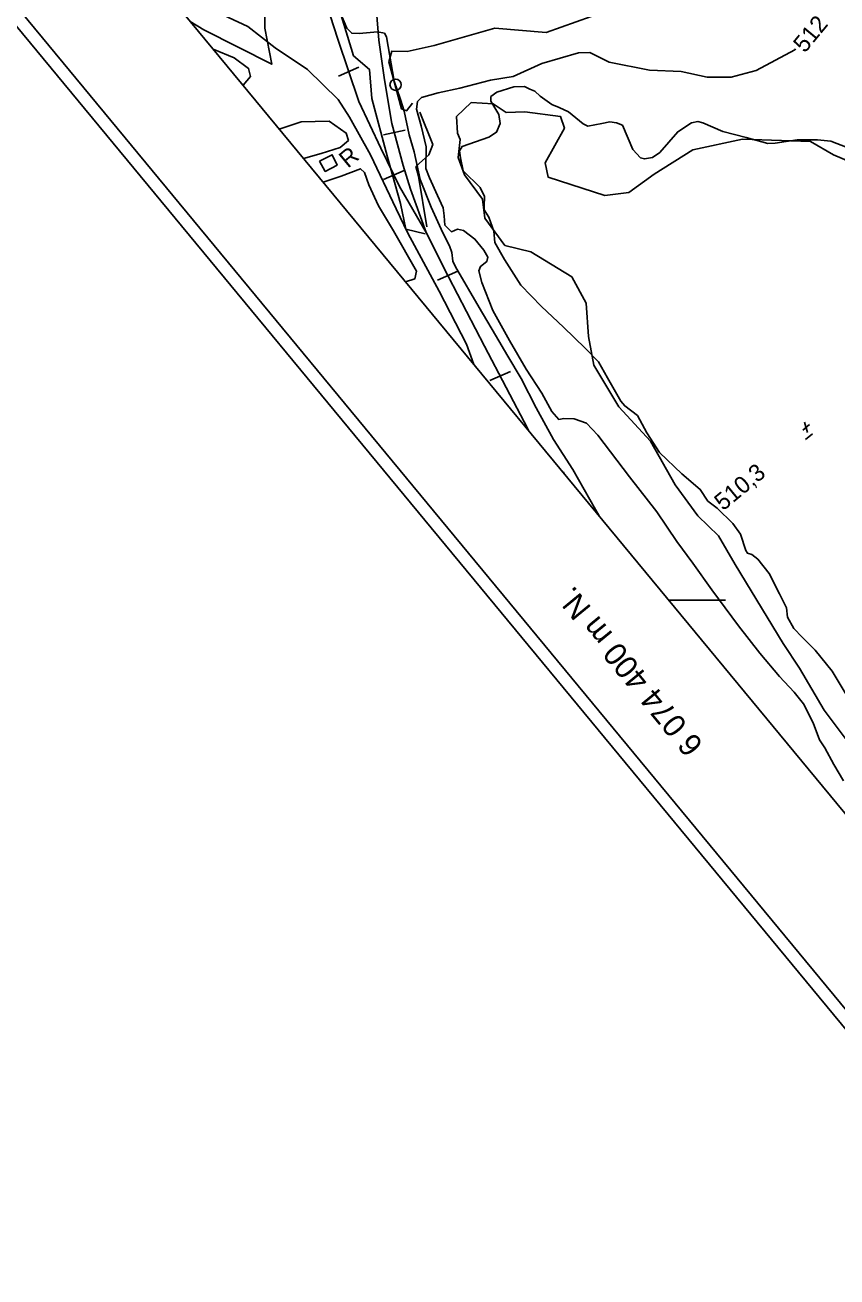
# Model space of a CAD drawing. Extents: x 347059 to 352153, y 6073752 to 6078601.
# Drawn here: x 348064.6 to 348279.8, y 6074220.5 to 6074552.6 of the extents above; entities that cross this region are included whole.
import ezdxf

# ---------------------------------------------------------------- set-up
doc = ezdxf.new("R2010")
doc.units = 0
for name, color, linetype in [('Level 1', 7, 'Continuous'), ('Level 2', 7, 'Continuous'), ('Level 23', 7, 'Continuous'), ('Level 3', 7, 'Continuous'), ('Level 31', 7, 'Continuous'), ('Level 36', 7, 'Continuous'), ('Level 4', 7, 'Continuous'), ('Level 44', 7, 'Continuous'), ('Level 60', 7, 'Continuous'), ('Level 61', 7, 'Continuous')]:
    doc.layers.add(name, color=color, linetype=linetype)

msp = doc.modelspace()

# ---------------------------------------------------------------- linework, layer by layer
at = {"layer": 'Level 1'}
for points in [[(348114.45, 6074546.2), (348119.99, 6074543.87), (348123.83, 6074541.07), (348124.38, 6074538.97), (348122.37, 6074536.61)], [(348131.99, 6074524.96), (348137.81, 6074526.94), (348145.22, 6074527.06), (348149.75, 6074523.92), (348150.32, 6074521.98), (348148.13, 6074520.13), (348143.07, 6074518.51), (348138.39, 6074517.22)], [(348143.59, 6074510.93), (348148.38, 6074512.54), (348153.47, 6074514.45), (348154.55, 6074513.49), (348155.73, 6074510.19), (348158.32, 6074504.59), (348162.28, 6074498), (348168.4, 6074487.34), (348167.89, 6074485.26), (348165.47, 6074484.45)]]:
    msp.add_lwpolyline(points, dxfattribs=at)
at = {"layer": 'Level 2'}
for points in [[(348145.31, 6074562.71), (348149.92, 6074551.73), (348151.18, 6074550.39), (348153.13, 6074550.3), (348158.05, 6074550.75), (348159.87, 6074550.4), (348160.44, 6074549.41), (348162.45, 6074537.69), (348164.15, 6074532.83), (348165.13, 6074529.77), (348166.43, 6074523.49), (348167.72, 6074518.96), (348169.37, 6074511.63), (348172.24, 6074504.27), (348175.31, 6074497.48), (348177.13, 6074494.06), (348177.71, 6074492.27), (348177.95, 6074489.93), (348178.69, 6074488.41), (348184.98, 6074477.65), (348189.31, 6074470.32), (348192.57, 6074464.78)], [(348113.37, 6074556.93), (348123.65, 6074552.15), (348130.88, 6074546.54), (348139.44, 6074540.77), (348147.55, 6074532.83), (348150.56, 6074528.14), (348156.2, 6074518.14), (348163.01, 6074503.86), (348166.02, 6074497.37)], [(348217.52, 6074543.71), (348214.32, 6074545.28), (348211.27, 6074545.24), (348201.55, 6074542.34), (348194.02, 6074538.89), (348188, 6074537.93), (348179.86, 6074535.84), (348174.11, 6074534.57), (348169.66, 6074533.34), (348168.63, 6074532.33)], [(348268.88, 6074546.23), (348268.66, 6074546.02), (348258.37, 6074540.48), (348251.79, 6074538.77), (348245.42, 6074538.71), (348238.52, 6074540.23), (348230.16, 6074540.63), (348219.4, 6074542.75), (348217.52, 6074543.71)], [(348168.63, 6074532.33), (348168.39, 6074530.24), (348169.56, 6074525.85), (348170.91, 6074520.29), (348170.81, 6074514.55), (348171.84, 6074512.06), (348173.92, 6074507.38), (348175.47, 6074504.12), (348175.66, 6074502), (348175.89, 6074499.5), (348177.63, 6074497.76), (348179.21, 6074498.43), (348180.84, 6074498.08), (348183.85, 6074495.79), (348186.22, 6074492.83), (348187.23, 6074491), (348186.99, 6074489.86), (348185.29, 6074488.54), (348184.9, 6074487.41), (348185.67, 6074484.29), (348188.61, 6074476.85), (348193.04, 6074468.91), (348197.42, 6074461.35), (348201.62, 6074454.96), (348204.26, 6074450.09), (348206.05, 6074447.98), (348207.45, 6074448.23), (348210.19, 6074448.15), (348213.43, 6074447.01), (348216.43, 6074443.78), (348224.81, 6074432.76), (348232.1, 6074423.5), (348237.4, 6074415.58), (348241.66, 6074409.88), (348246.68, 6074402.79), (348253.69, 6074393.2), (348259.36, 6074385.99), (348264.6, 6074379.77), (348268.48, 6074375.63), (348270.93, 6074372.57), (348273.56, 6074367.53), (348275.22, 6074363), (348276.65, 6074360.84), (348278.98, 6074356.47), (348281.6, 6074352.09)], [(348166.02, 6074497.37), (348174.35, 6074481.97), (348181.59, 6074467.9), (348183.6, 6074462.51)], [(348192.57, 6074464.78), (348196.11, 6074458.79), (348200.11, 6074451.05), (348204.65, 6074442.68), (348209.79, 6074434.7), (348215.8, 6074424.1), (348216.77, 6074422.37)]]:
    msp.add_lwpolyline(points, dxfattribs=at)
at = {"layer": 'Level 23'}
for points in [[(348170.93, 6074497.59), (348163.82, 6074509.8), (348158.89, 6074519.94), (348153.07, 6074532.32), (348147.46, 6074548.86), (348144.53, 6074558.12), (348140.41, 6074572.6), (348139.1, 6074584.7)], [(348198.25, 6074444.78), (348197.9, 6074445.44), (348186.42, 6074467.4), (348176.81, 6074485.77), (348170.93, 6074497.59), (348166.73, 6074509.01), (348164.82, 6074515.35), (348161.82, 6074526.5), (348159.85, 6074538.04), (348158.35, 6074548.56), (348157.46, 6074559.44)], [(348153.1, 6074541.4), (348147.68, 6074539.04)], [(348165.37, 6074524.68), (348159.58, 6074523.46)], [(348165.06, 6074514.02), (348159.64, 6074511.65)], [(348179.34, 6074487.32), (348173.91, 6074484.95)], [(348193.25, 6074460.7), (348187.83, 6074458.34)]]:
    msp.add_lwpolyline(points, dxfattribs=at)
at = {"layer": 'Level 3'}
for p, q in [((348271.21, 6074447.28), (348272.04, 6074444.53)), ((348270.75, 6074445.15), (348272.56, 6074446.64)), ((348271.47, 6074442.63), (348273.32, 6074444.16))]:
    msp.add_line(p, q, dxfattribs=at)
at = {"layer": 'Level 31'}
msp.add_lwpolyline([(348142.63, 6074516.5), (348146.02, 6074518.19), (348147.28, 6074515.42), (348144.18, 6074513.74), (348142.63, 6074516.5)], dxfattribs=at)
at = {"layer": 'Level 36'}
msp.add_circle((348162.81, 6074536.75), 1.5, dxfattribs=at)
at = {"layer": 'Level 4'}
for points in [[(348196.02, 6074483.59), (348191.68, 6074490.43), (348189.13, 6074494.93), (348188.83, 6074497.91), (348187.56, 6074501.59), (348186.27, 6074503.6), (348186.31, 6074504.54), (348186.38, 6074507.07), (348185.2, 6074509.48), (348180.72, 6074513.95), (348180.05, 6074517.37), (348179.77, 6074519.24), (348180.49, 6074520.37), (348182.23, 6074520.99), (348187.56, 6074522.8), (348189.61, 6074524.13), (348190.57, 6074526.5), (348190.17, 6074528.87), (348188.07, 6074532.39), (348188.1, 6074533.61), (348189.64, 6074534.75), (348194.2, 6074536.22), (348196.96, 6074536.25), (348198.37, 6074535.55), (348199.72, 6074535.01), (348201.16, 6074533.73), (348204.21, 6074531.53), (348206.18, 6074530.69), (348208.67, 6074529.6), (348212.52, 6074526.34), (348213.82, 6074525.77), (348217.46, 6074526.46), (348219.63, 6074526.92), (348221.42, 6074526.68), (348222.96, 6074526), (348225.7, 6074519.56), (348227.75, 6074517.36), (348228.83, 6074517.06), (348230.89, 6074517.48), (348232.85, 6074518.74), (348237.62, 6074524.29), (348241.29, 6074526.67), (348242.92, 6074526.97), (348244.29, 6074526.68), (348249.54, 6074524.35), (348255.76, 6074522.76), (348261.53, 6074521.17), (348263.42, 6074521.24), (348269.29, 6074522.14), (348274.63, 6074522.14), (348278.17, 6074521.78), (348282.54, 6074520.07)], [(348282.54, 6074374.57), (348278.58, 6074381.21), (348274.04, 6074386.75), (348270.58, 6074390.27), (348268.37, 6074392.56), (348266.75, 6074395.5), (348266.44, 6074398.03), (348264.6, 6074401.69), (348261.85, 6074407.15), (348258.87, 6074410.91), (348257.3, 6074412.16), (348256.1, 6074412.51), (348255.63, 6074413.17), (348254.22, 6074417.57), (348252.26, 6074420.37), (348248.11, 6074424.44), (348245.57, 6074426.32), (348243.6, 6074429.41), (348238.68, 6074433.59), (348232.82, 6074439.17), (348229.4, 6074444.45), (348226.98, 6074448.98), (348223.56, 6074451.54), (348222.49, 6074452.83), (348219.03, 6074458.97), (348216.62, 6074463.21), (348213.05, 6074466.86), (348207.36, 6074472.43), (348201.5, 6074477.92), (348196.02, 6074483.59)]]:
    msp.add_lwpolyline(points, dxfattribs=at)
at = {"layer": 'Level 44'}
for points in [[(348108.37, 6074553.56), (348111.99, 6074551.35), (348129.99, 6074542.19), (348128.16, 6074551.75), (348128.25, 6074563.51), (348133.69, 6074573.89), (348144.19, 6074568.84), (348151.63, 6074544.45), (348155.87, 6074540.8), (348156.48, 6074533.06), (348160.71, 6074517.55), (348164.09, 6074505.23), (348165.52, 6074498.48), (348170.62, 6074497.16)], [(348167.31, 6074531.88), (348165.72, 6074529.84), (348164.37, 6074530.38), (348161.01, 6074542.86), (348161.84, 6074545.65), (348165.84, 6074545.53), (348173.02, 6074547.17), (348189.16, 6074551.74), (348202.73, 6074550.59), (348214.66, 6074554.82)], [(348288.71, 6074513.99), (348278.91, 6074518.17), (348272.83, 6074521.67), (348254.83, 6074522.33), (348241.6, 6074519.44), (348231.33, 6074513), (348224.66, 6074508.2), (348218.27, 6074507.39), (348203.28, 6074512.2), (348202.48, 6074516.05), (348207.59, 6074525.26), (348206.55, 6074528.3), (348197.07, 6074529.58), (348192.12, 6074529.37), (348188.72, 6074531.65), (348182.85, 6074532.02), (348178.99, 6074528.36), (348179.24, 6074523.91), (348179.9, 6074522.22), (348179.39, 6074517.43), (348181.1, 6074512.84), (348185.85, 6074506.43), (348186.46, 6074501.37), (348191.78, 6074494.08), (348198.69, 6074492.46), (348209.5, 6074485.82), (348213.37, 6074478.82), (348213.97, 6074469.99), (348215.33, 6074462.41), (348222.03, 6074451.3), (348230.39, 6074442.18), (348236.97, 6074430.67), (348242.94, 6074422.43), (348248.44, 6074417.09), (348252.84, 6074409.48), (348265.61, 6074388.56), (348269.86, 6074382.03), (348276.47, 6074370.86), (348285.16, 6074359.16)], [(348171.11, 6074499.08), (348168.86, 6074512.51), (348168.19, 6074515.1), (348171.66, 6074518.14), (348172.65, 6074520.92), (348169.26, 6074529.48)], [(348207.49, 6074433.6), (348207.21, 6074434.09)]]:
    msp.add_lwpolyline(points, dxfattribs=at)
at = {"layer": 'Level 60'}
msp.add_line((348235.25, 6074400), (348250.32, 6074400), dxfattribs=at)
msp.add_lwpolyline([(347109.95, 6075761.81), (348728.53, 6073803.05), (351407.22, 6076016.53), (349788.63, 6077975.29)], close=True, dxfattribs=at)
for points in [[(347058.77, 6075766.69), (348723.67, 6073751.88)], [(347063.49, 6075766.23), (348724.12, 6073756.59)]]:
    msp.add_lwpolyline(points, dxfattribs=at)

# ---------------------------------------------------------------- texts
at = {"layer": 'Level 2'}
msp.add_text('512', height=4.5, rotation=50.5209, dxfattribs=at).set_placement((348271.32, 6074544.98))
at = {"layer": 'Level 3'}
msp.add_text('  510,3', height=4.5, rotation=39.57, dxfattribs=at).set_placement((348247.08, 6074421.46))
at = {"layer": 'Level 31'}
msp.add_text('R', height=4.5, rotation=39.5623, dxfattribs=at).set_placement((348150.16, 6074514.46))
at = {"layer": 'Level 61'}
msp.add_text('6 074 400 m N.', height=6, rotation=129.3644, dxfattribs=at).set_placement((348244.65, 6074361.77))

doc.saveas('drawing.dxf')
